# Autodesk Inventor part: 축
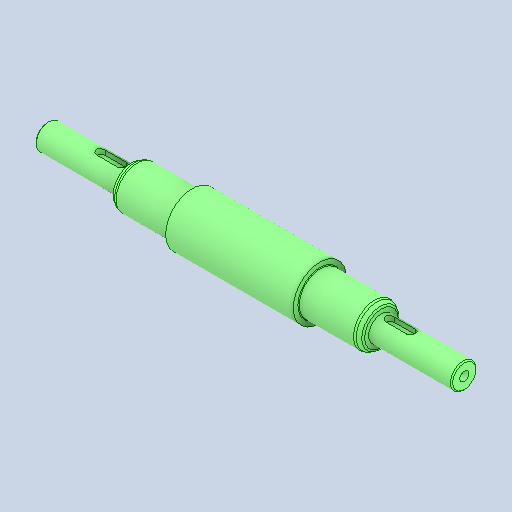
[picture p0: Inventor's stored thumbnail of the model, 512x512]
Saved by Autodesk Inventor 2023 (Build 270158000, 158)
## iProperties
Created: 2026-06
Part Number: 축
Material: 강철, 탄소
Document SubType Name: Modeling
Designer: 4강의실
Density: 7.85 g/cm^3
Appearance: 기본값
Author: jhkim
Sending System: Autodesk Inventor 2027
Preprocessor: ST-DEVELOPER v20.1
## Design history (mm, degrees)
feature "솔리드1"
node "솔리드2"
